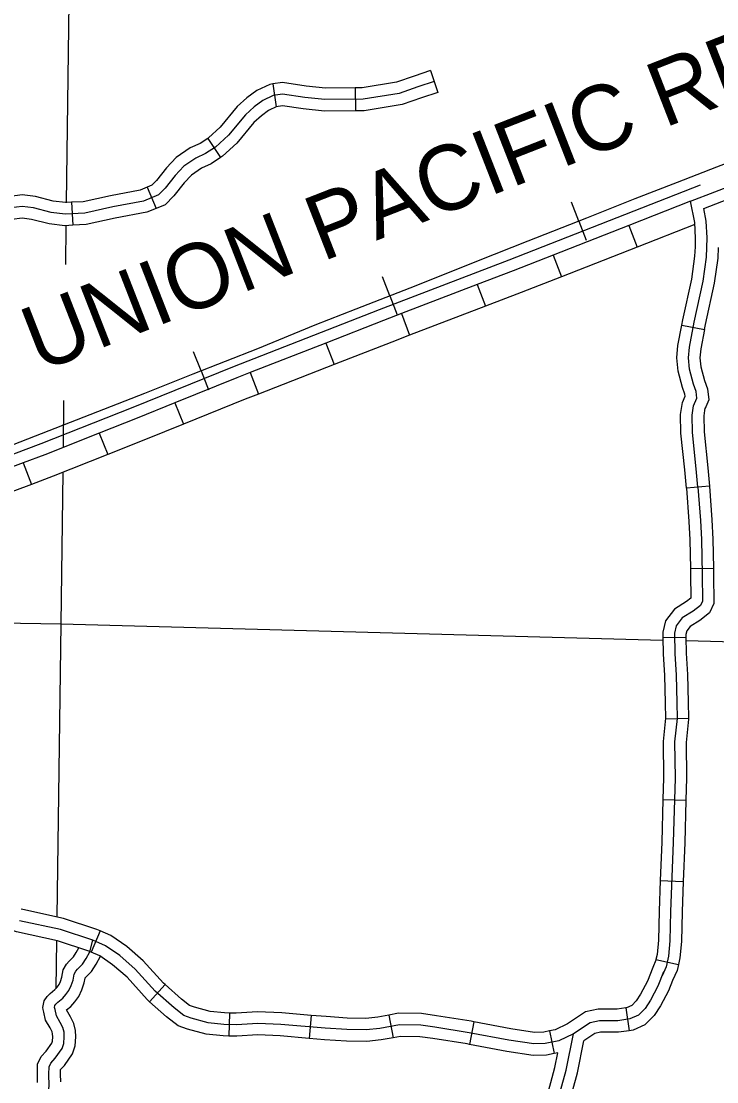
# Model space of a CAD drawing. Extents: x 8749 to 11879, y 13275 to 15339.
# Drawn here: x 10737.1 to 10827.5, y 13692.2 to 13830 of the extents above; entities that cross this region are included whole.
import ezdxf

# ---------------------------------------------------------------- set-up
doc = ezdxf.new("R2010")
doc.units = 0
for name, color, linetype in [('Level 31', 7, 'Continuous'), ('Level 32', 7, 'Continuous'), ('Level 35', 7, 'Continuous'), ('Level 40', 7, 'Continuous'), ('Level 45', 7, 'Continuous'), ('Level 5', 7, 'Continuous')]:
    doc.layers.add(name, color=color, linetype=linetype)

msp = doc.modelspace()

# ---------------------------------------------------------------- linework, layer by layer
at = {"layer": 'Level 31'}
for p, q in [((10822.96, 13790.52), (10825.91, 13789.96)), ((10826.53, 13769.59), (10823.54, 13769.33)), ((10826.53, 13769.57), (10823.54, 13769.35)), ((10823.54, 13769.35), (10823.54, 13769.33))]:
    msp.add_line(p, q, dxfattribs=at)
for points in [[(10825.81, 13805.66), (10837.15, 13810.07), (10849.45, 13814.65), (10854.39, 13816.6)], [(10824.71, 13800.69), (10824.75, 13801.81), (10824.63, 13803.82), (10824.1, 13806.61), (10830.39, 13809.05)], [(10824.83, 13771.84), (10824.34, 13776.55), (10824.3, 13778.82), (10824.47, 13780.02), (10824.92, 13781.04), (10824.83, 13781.89), (10824.47, 13782.84), (10823.94, 13784.8), (10823.81, 13786.27), (10823.94, 13787.65), (10824.56, 13790.89), (10825.72, 13796.23), (10826.16, 13799.34), (10826.25, 13801.83), (10826.12, 13804.01), (10825.81, 13805.66)], [(10822.96, 13790.52), (10823.09, 13791.19), (10824.24, 13796.49), (10824.66, 13799.47), (10824.71, 13800.69)], [(10825.91, 13789.96), (10826.03, 13790.59), (10827.19, 13795.96), (10827.66, 13799.21), (10827.71, 13800.58)], [(10822.98, 13780.19), (10823.02, 13780.44), (10823.38, 13781.28), (10823.36, 13781.54), (10823.04, 13782.39), (10822.46, 13784.53), (10822.3, 13786.27), (10822.45, 13787.86), (10822.96, 13790.52)], [(10825.91, 13789.96), (10825.43, 13787.43), (10825.31, 13786.26), (10825.42, 13785.07), (10825.9, 13783.3), (10826.3, 13782.23), (10826.45, 13780.81), (10825.93, 13779.61)], [(10823.54, 13769.33), (10823.34, 13771.7), (10822.84, 13776.46), (10822.79, 13778.92), (10822.98, 13780.19)], [(10825.95, 13779.75), (10825.8, 13778.72), (10825.84, 13776.65), (10826.32, 13771.98), (10826.53, 13769.59)], [(10825.04, 13769.46), (10824.83, 13771.84)]]:
    msp.add_lwpolyline(points, dxfattribs=at)
at = {"layer": 'Level 32'}
for p, q in [((10790.29, 13823.58), (10791.24, 13820.73)), ((10769.8, 13821.84), (10770.24, 13818.87)), ((10780.51, 13821.33), (10780.53, 13818.33)), ((10761.33, 13814.76), (10762.98, 13812.26)), ((10753.47, 13808.43), (10754.61, 13805.65)), ((10743.64, 13806.46), (10743.8, 13803.47)), ((10816.05, 13803.45), (10817.14, 13800.65)), ((10806.22, 13799.6), (10807.31, 13796.8)), ((10796.36, 13795.78), (10797.43, 13792.98)), ((10786.5, 13792), (10787.57, 13789.2)), ((10776.66, 13788.18), (10777.75, 13785.39)), ((10766.83, 13784.34), (10767.92, 13781.55)), ((10757.05, 13780.41), (10758.17, 13777.63)), ((10747.23, 13776.48), (10748.34, 13773.69)), ((10737.36, 13772.63), (10738.41, 13769.82)), ((10824.07, 13758.89), (10827.07, 13758.95)), ((10820.49, 13749.94), (10823.49, 13749.99)), ((10820.83, 13739.38), (10823.83, 13739.44)), ((10820.49, 13728.91), (10823.49, 13728.83)), ((10820.15, 13718.38), (10823.14, 13718.26)), ((10747.35, 13711.83), (10746.16, 13709.08)), ((10819.59, 13708.12), (10822.52, 13707.46)), ((10755.78, 13704.87), (10753.78, 13702.63)), ((10815.69, 13701.84), (10816.12, 13698.87)), ((10764.16, 13701.16), (10764.08, 13698.16)), ((10774.78, 13700.85), (10774.53, 13697.86)), ((10784.89, 13700.9), (10785.45, 13697.96)), ((10795.91, 13700.03), (10795.35, 13697.08)), ((10805.75, 13698.84), (10806.34, 13695.9))]:
    msp.add_line(p, q, dxfattribs=at)
for points in [[(10790.29, 13823.58), (10788.14, 13822.86), (10785.86, 13822.06), (10781.4, 13821.34), (10780.51, 13821.33)], [(10790.76, 13822.16), (10788.63, 13821.44), (10786.23, 13820.6), (10781.52, 13819.84), (10776.56, 13819.8), (10773.94, 13820.07), (10771.05, 13820.51), (10769.85, 13820.33), (10768.47, 13819.67), (10767.36, 13818.87), (10766.25, 13817.84), (10764.03, 13815.19), (10762.34, 13813.63), (10761.06, 13812.79), (10759.77, 13812.21), (10758.21, 13811.14), (10757.1, 13809.94), (10755.81, 13808.3), (10754.94, 13807.41), (10752.98, 13806.61), (10748.98, 13805.85), (10745.34, 13805.05), (10742.81, 13804.92), (10740.99, 13805.14), (10738.68, 13805.72), (10737.21, 13805.9), (10735.75, 13805.72)], [(10769.8, 13821.84), (10769.4, 13821.78), (10767.7, 13820.96), (10766.41, 13820.03), (10765.16, 13818.88), (10762.94, 13816.23), (10761.42, 13814.82), (10761.33, 13814.76)], [(10780.51, 13821.33), (10776.63, 13821.3), (10774.13, 13821.55), (10771.05, 13822.03), (10769.8, 13821.84)], [(10791.24, 13820.73), (10789.12, 13820.03), (10786.6, 13819.14), (10781.65, 13818.34), (10780.53, 13818.33)], [(10770.3, 13818.88), (10769.24, 13818.37), (10768.31, 13817.7), (10767.34, 13816.81), (10765.12, 13814.15), (10763.27, 13812.45), (10762.98, 13812.26)], [(10780.53, 13818.33), (10776.49, 13818.3), (10773.75, 13818.58), (10771.05, 13818.99), (10770.24, 13818.87)], [(10761.33, 13814.76), (10760.33, 13814.11), (10759.03, 13813.52), (10757.23, 13812.28), (10755.96, 13810.92), (10754.69, 13809.29), (10754.08, 13808.68), (10753.47, 13808.43)], [(10762.98, 13812.26), (10761.78, 13811.47), (10760.51, 13810.9), (10759.2, 13810), (10758.25, 13808.97), (10756.94, 13807.3), (10755.79, 13806.14), (10754.61, 13805.65)], [(10753.47, 13808.43), (10752.55, 13808.05), (10748.68, 13807.32), (10745.14, 13806.54), (10743.64, 13806.46)], [(10743.64, 13806.46), (10742.86, 13806.42), (10741.26, 13806.62), (10738.95, 13807.2), (10737.21, 13807.41), (10735.64, 13807.22), (10734.02, 13807.18), (10733.4, 13807.23)], [(10824.1, 13806.6), (10816.05, 13803.45)], [(10754.61, 13805.65), (10753.41, 13805.16), (10749.28, 13804.38), (10745.54, 13803.56), (10743.8, 13803.47)], [(10743.8, 13803.47), (10742.76, 13803.41), (10740.71, 13803.66), (10738.41, 13804.24), (10737.21, 13804.39), (10735.86, 13804.22), (10733.92, 13804.17), (10733.14, 13804.24)], [(10816.05, 13803.45), (10806.22, 13799.6)], [(10824.64, 13803.59), (10817.14, 13800.65)], [(10806.22, 13799.6), (10801.01, 13797.56), (10796.36, 13795.78)], [(10817.14, 13800.65), (10807.31, 13796.8)], [(10807.31, 13796.8), (10802.09, 13794.76), (10797.43, 13792.98)], [(10796.36, 13795.78), (10786.5, 13792)], [(10797.43, 13792.98), (10787.57, 13789.2)], [(10786.5, 13792), (10784.17, 13791.11), (10776.66, 13788.18)], [(10787.57, 13789.2), (10785.26, 13788.31), (10777.75, 13785.39)], [(10776.66, 13788.18), (10766.83, 13784.34)], [(10766.83, 13784.34), (10765.09, 13783.66), (10757.05, 13780.41)], [(10777.75, 13785.39), (10767.92, 13781.55)], [(10757.05, 13780.41), (10752.14, 13778.42), (10747.23, 13776.48)], [(10767.92, 13781.55), (10766.2, 13780.88), (10758.17, 13777.63)], [(10758.17, 13777.63), (10753.25, 13775.64), (10748.34, 13773.69)], [(10747.23, 13776.48), (10740.17, 13773.67), (10737.36, 13772.63)], [(10748.34, 13773.69), (10741.24, 13770.87), (10738.41, 13769.82)], [(10737.36, 13772.63), (10731.05, 13770.29), (10727.47, 13768.95)], [(10738.41, 13769.82), (10732.1, 13767.48), (10728.52, 13766.14)], [(10825.04, 13769.46), (10825.36, 13765.11), (10825.49, 13762.66), (10825.58, 13758.13), (10825.63, 13754.66), (10825.36, 13754.08), (10824.43, 13753.37), (10823.01, 13752.48), (10822.21, 13751.46), (10821.99, 13750.48), (10822.03, 13747.86), (10822.2, 13745.04), (10822.29, 13741.49), (10822.33, 13739.4), (10822.02, 13736.37), (10822.07, 13731.68), (10821.84, 13723.32), (10821.49, 13714.34), (10821.4, 13710.54), (10821.22, 13708.54), (10820.91, 13707.16), (10820.38, 13706.01)], [(10823.54, 13769.35), (10823.86, 13765.01), (10824, 13762.61), (10824.07, 13758.89)], [(10826.53, 13769.57), (10826.86, 13765.21), (10826.99, 13762.72), (10827.07, 13758.95)], [(10824.07, 13758.89), (10824.08, 13758.1), (10824.12, 13755.03), (10823.57, 13754.61), (10821.99, 13753.61), (10820.82, 13752.12), (10820.48, 13750.64), (10820.49, 13749.94)], [(10827.07, 13758.95), (10827.08, 13758.15), (10827.13, 13754.34), (10826.57, 13753.12), (10825.28, 13752.14), (10824.03, 13751.35), (10823.6, 13750.8), (10823.49, 13750.33), (10823.49, 13749.99)], [(10820.49, 13749.94), (10820.53, 13747.8), (10820.7, 13744.98), (10820.79, 13741.45), (10820.83, 13739.38)], [(10823.49, 13749.99), (10823.53, 13747.92), (10823.7, 13745.11), (10823.79, 13741.52), (10823.83, 13739.44)], [(10820.83, 13739.46), (10820.52, 13736.44), (10820.57, 13731.69), (10820.49, 13728.91)], [(10823.83, 13739.44), (10823.83, 13739.34), (10823.52, 13736.3), (10823.57, 13731.67), (10823.49, 13728.83)], [(10820.49, 13728.91), (10820.34, 13723.37), (10820.15, 13718.38)], [(10823.49, 13728.83), (10823.34, 13723.27), (10823.14, 13718.26)], [(10820.15, 13718.38), (10819.99, 13714.39), (10819.9, 13710.62), (10819.74, 13708.77), (10819.59, 13708.12)], [(10823.14, 13718.26), (10822.99, 13714.29), (10822.9, 13710.45), (10822.71, 13708.31), (10822.52, 13707.46)], [(10747.35, 13711.83), (10746.93, 13712.01), (10742.6, 13713.45), (10737.28, 13714.6), (10737.08, 13714.67)], [(10820.59, 13706.53), (10819.83, 13704.66), (10818.9, 13702.84), (10818.19, 13701.77), (10817.3, 13700.88), (10816.19, 13700.39), (10814.63, 13700.17), (10812.24, 13700.17), (10811.04, 13699.9), (10808.86, 13698.46), (10806.95, 13697.55), (10805.17, 13697.19), (10803.71, 13697.15), (10800.47, 13697.64), (10795.31, 13698.61), (10790.83, 13699.33), (10789.01, 13699.59), (10786.25, 13699.64), (10783.68, 13699.15), (10781.94, 13698.97), (10779.41, 13699.01), (10776.61, 13699.19), (10770.84, 13699.68), (10767.82, 13699.81), (10765.07, 13699.64), (10763.42, 13699.68), (10761.38, 13699.9), (10759.16, 13700.48), (10758.23, 13700.84), (10756.95, 13701.82), (10754.51, 13703.99), (10751.89, 13706.88), (10749.89, 13708.62), (10748.02, 13709.91), (10746.4, 13710.61), (10742.21, 13712), (10736.88, 13713.15)], [(10746.16, 13709.08), (10745.87, 13709.2), (10741.81, 13710.55), (10736.47, 13711.71), (10736.1, 13711.83)], [(10755.78, 13704.87), (10755.57, 13705.06), (10752.94, 13707.96), (10750.81, 13709.8), (10748.75, 13711.23), (10747.35, 13711.83)], [(10753.78, 13702.63), (10753.45, 13702.93), (10750.84, 13705.81), (10748.97, 13707.43), (10747.29, 13708.59), (10746.16, 13709.08)], [(10819.59, 13708.12), (10819.57, 13708.02), (10819.19, 13707.09), (10818.47, 13705.28), (10817.6, 13703.6), (10817.02, 13702.73), (10816.44, 13702.14), (10815.77, 13701.85), (10815.69, 13701.84)], [(10822.52, 13707.46), (10822.34, 13706.67), (10821.74, 13705.37), (10821.2, 13704.04), (10820.2, 13702.08), (10819.35, 13700.82), (10818.16, 13699.62), (10816.61, 13698.94), (10816.12, 13698.87)], [(10764.16, 13701.16), (10763.52, 13701.18), (10761.65, 13701.38), (10759.62, 13701.91), (10758.97, 13702.16), (10757.91, 13702.97), (10755.78, 13704.87)], [(10764.08, 13698.16), (10763.32, 13698.18), (10761.11, 13698.42), (10758.7, 13699.05), (10757.49, 13699.51), (10755.99, 13700.66), (10753.78, 13702.63)], [(10815.69, 13701.84), (10814.53, 13701.67), (10812.07, 13701.67), (10810.44, 13701.31), (10808.11, 13699.77), (10806.47, 13698.98), (10805.75, 13698.84)], [(10774.78, 13700.85), (10770.94, 13701.18), (10767.81, 13701.32), (10765.04, 13701.14), (10764.16, 13701.16)], [(10784.89, 13700.9), (10783.46, 13700.63), (10781.88, 13700.47), (10779.47, 13700.51), (10776.73, 13700.69), (10774.78, 13700.85)], [(10795.91, 13700.03), (10795.57, 13700.09), (10791.05, 13700.81), (10789.13, 13701.09), (10786.12, 13701.14), (10784.89, 13700.9)], [(10805.75, 13698.84), (10805, 13698.69), (10803.8, 13698.65), (10800.72, 13699.11), (10795.91, 13700.03)], [(10774.53, 13697.86), (10770.74, 13698.18), (10767.84, 13698.31), (10765.09, 13698.14), (10764.08, 13698.16)], [(10785.45, 13697.96), (10783.89, 13697.66), (10782.01, 13697.47), (10779.35, 13697.52), (10776.5, 13697.7), (10774.53, 13697.86)], [(10795.35, 13697.08), (10795.06, 13697.14), (10790.6, 13697.84), (10788.89, 13698.09), (10786.38, 13698.13), (10785.45, 13697.96)], [(10807.94, 13687.87), (10808.18, 13688.99), (10809.38, 13693.41), (10810.21, 13697.56)], [(10816.12, 13698.87), (10814.74, 13698.67), (10812.4, 13698.67), (10811.63, 13698.5), (10810.21, 13697.56)], [(10806.34, 13695.9), (10805.35, 13695.7), (10803.62, 13695.64), (10800.21, 13696.16), (10795.35, 13697.08)], [(10805.01, 13688.5), (10805.27, 13689.71), (10806.46, 13694.09), (10806.84, 13695.99)], [(10806.84, 13695.99), (10806.34, 13695.9)]]:
    msp.add_lwpolyline(points, dxfattribs=at)
at = {"layer": 'Level 35'}
msp.add_lwpolyline([(10825.33, 13808.7), (10800.47, 13798.96), (10783.63, 13792.51), (10764.53, 13785.06), (10751.58, 13779.81), (10739.63, 13775.07), (10730.52, 13771.69), (10724.71, 13769.52), (10721.33, 13767.69), (10714.8, 13763.91), (10710.63, 13761.42), (10708.09, 13760.22), (10706.39, 13760.2)], dxfattribs=at)
at = {"layer": 'Level 40'}
for p, q in [((10809.56, 13804), (10808.6, 13806.46)), ((10809.56, 13804), (10810.52, 13801.53)), ((10785, 13794.31), (10784.05, 13796.77)), ((10785, 13794.31), (10785.96, 13791.85)), ((10760.46, 13784.57), (10759.5, 13787.03)), ((10760.46, 13784.57), (10761.43, 13782.11))]:
    msp.add_line(p, q, dxfattribs=at)
for points in [[(10859.37, 13823.46), (10852.26, 13820.69), (10846.63, 13818.51), (10841.88, 13816.68), (10838.3, 13815.27), (10831.74, 13812.65), (10827.46, 13811.01), (10822.33, 13809.01), (10816.86, 13806.89), (10810.58, 13804.39), (10802.93, 13801.42), (10796.47, 13798.86), (10788.36, 13795.61), (10780.59, 13792.6), (10775.27, 13790.5), (10767.78, 13787.44), (10759.38, 13784.15), (10753.12, 13781.63), (10747, 13779.26)], [(10831.74, 13812.65), (10827.46, 13811.01), (10822.33, 13809.01), (10816.86, 13806.89), (10810.58, 13804.39), (10802.93, 13801.42), (10796.47, 13798.86), (10788.36, 13795.61), (10780.59, 13792.6), (10775.27, 13790.5), (10767.78, 13787.44), (10759.38, 13784.15), (10753.12, 13781.63), (10747, 13779.26), (10733.3, 13773.93)], [(10747, 13779.26), (10733.3, 13773.93), (10723.75, 13770.14), (10708.22, 13764.16), (10703.54, 13762.32), (10692.19, 13757.94), (10688.04, 13756.32), (10678.82, 13752.73), (10666.84, 13748.13), (10657.15, 13744.3), (10652.29, 13742.36)]]:
    msp.add_lwpolyline(points, dxfattribs=at)
at = {"layer": 'Level 45'}
for points in [[(10742.68, 13698.08), (10742.65, 13698.67), (10742.5, 13699.27), (10742.16, 13699.93), (10741.67, 13700.79), (10741.48, 13701.6), (10741.43, 13701.9), (10741.47, 13702.16), (10741.59, 13702.32), (10741.85, 13702.59), (10742.48, 13703.11), (10742.9, 13703.58), (10743.29, 13704.08), (10743.58, 13704.73), (10743.82, 13705.45), (10743.97, 13706.23), (10744.19, 13706.61), (10744.42, 13706.87), (10745.05, 13707.51), (10745.52, 13708.26), (10746, 13709.13), (10746.4, 13710.61)], [(10739.95, 13701.62), (10739.9, 13701.89), (10740.05, 13702.76), (10740.44, 13703.29), (10740.83, 13703.69), (10741.44, 13704.2), (10741.75, 13704.54), (10742, 13704.86), (10742.18, 13705.27), (10742.37, 13705.83), (10742.54, 13706.76), (10742.97, 13707.49), (10743.32, 13707.89), (10743.86, 13708.44), (10744.23, 13709.02), (10744.57, 13709.63)], [(10742.96, 13701.56), (10743.52, 13702.03), (10744.05, 13702.62), (10744.59, 13703.3), (10744.98, 13704.18), (10745.28, 13705.07), (10745.4, 13705.69), (10745.41, 13705.72), (10745.52, 13705.85), (10746.23, 13706.57), (10746.82, 13707.5), (10747.38, 13708.53)], [(10739.22, 13692.14), (10739.19, 13693.23), (10739.22, 13694.51), (10739.67, 13695.5), (10740.34, 13696.22), (10741.05, 13697.25), (10741.14, 13697.51), (10741.18, 13698.08), (10741.16, 13698.45), (10741.09, 13698.74), (10740.84, 13699.22), (10740.26, 13700.24), (10740.01, 13701.29), (10739.95, 13701.63)], [(10742.22, 13692.23), (10742.19, 13693.24), (10742.21, 13693.82), (10742.69, 13694.34), (10743.75, 13695.88), (10744.11, 13696.91), (10744.18, 13698.07), (10744.14, 13698.89), (10743.92, 13699.79), (10743.48, 13700.65), (10742.96, 13701.56)], [(10740.58, 13686.7), (10740.4, 13687.76), (10740.43, 13689.1), (10740.56, 13690.19), (10740.74, 13691.72), (10740.69, 13693.23), (10740.72, 13694.17), (10740.94, 13694.65), (10741.51, 13695.28), (10742.4, 13696.57), (10742.63, 13697.21), (10742.68, 13698.08)], [(10770.93, 13518.58), (10773.55, 13530.43), (10775.32, 13539.14), (10778.43, 13553.7), (10783.18, 13576.4), (10787.09, 13595.66), (10790.82, 13613.72), (10794.07, 13628.79), (10796.15, 13639.48), (10798.95, 13652.66), (10801.26, 13663.33), (10804.77, 13680.37), (10806.72, 13689.35), (10807.92, 13693.75), (10808.86, 13698.46)]]:
    msp.add_lwpolyline(points, dxfattribs=at)
at = {"layer": 'Level 5'}
for points in [[(10743.61, 13858.47), (10742.94, 13806.41)], [(10742.9, 13803.42), (10742.83, 13798.36)], [(10742.6, 13780.7), (10742.52, 13774.61)], [(10742.48, 13771.36), (10742.23, 13751.69)], [(10710.78, 13752.21), (10742.23, 13751.69)], [(10742.23, 13751.69), (10741.71, 13713.64)], [(10742.23, 13751.69), (10820.5, 13749.61)], [(10823.5, 13749.53), (10848.7, 13748.87)], [(10741.67, 13710.59), (10741.59, 13704.32)]]:
    msp.add_lwpolyline(points, dxfattribs=at)

# ---------------------------------------------------------------- texts
at = {"layer": 'Level 40'}
msp.add_text('UNION PACIFIC RR.', height=8.448, rotation=21.3423, dxfattribs=at).set_placement((10739.39, 13784.33))

doc.saveas('drawing.dxf')
